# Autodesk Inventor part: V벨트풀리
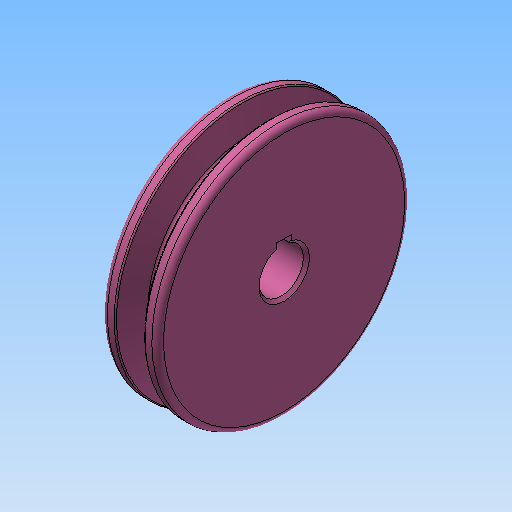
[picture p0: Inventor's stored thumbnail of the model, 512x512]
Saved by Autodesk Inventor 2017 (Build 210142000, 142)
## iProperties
Created: 2018-11
Part Number: V벨트풀리
Material: 알루미늄 6061
Document SubType Name: Modeling
Designer: mduedu
Density: 1 g/cm^3
Appearance: 분홍색
Author: mduedu
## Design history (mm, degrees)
sketch "스케치1"
  geometry: L1 (-9.5, 0)-(9.5, 0); L2 (9.5, 0)-(9.5, 42.7); L3 (9.5, 42.7)-(4.877, 42.7); L4 (-9.5, 42.7)-(-9.5, 0); L5 (-4.877, 42.7)-(-1.953, 33.7); L6 (-1.953, 33.7)-(1.953, 33.7); L7 (1.953, 33.7)-(4.877, 42.7); L8 (0, 0)-(0, 42.7); L9 (-9.5, 40)-(9.5, 40); L10 (-4.877, 42.7)-(-9.5, 42.7); L11 (4.877, 42.7)-(-4.877, 42.7); 3 further points
  constraints: 22 end point, 6 point on line, 4 parallel, 3 perpendicular, 2 midpoint, 1 coincident, 1 horizontal, 1 vertical, 1 other
  dimensions: "d2" = 19 distance of L2.end L4.start; "d3" = 80 diameter of L9 L1; "d4" = 36 deg angle of L7 L5; "d5" = 6.3 distance between parallel lines of L6 L9; "d6" = 8 distance of point (4, 40) point (-4, 40); "d27" = 2.7 distance between parallel lines of L3 L9
revolve "회전1" sketch "스케치1" stored, may be unused: angle "d7" = 90 deg
sketch "스케치2"
  geometry: L1 (-2.5, 7.071)-(2.5, 7.071); L2 (2.5, 7.071)-(2.5, 9.8); L3 (2.5, 9.8)-(-2.5, 9.8); L4 (-2.5, 9.8)-(-2.5, 7.071); A1 r 7.5 centre (0, 0) between (-2.5, 7.071) and (2.5, 7.071); 1 further point
  constraints: 8 end point, 2 parallel, 2 point on circle, 1 centre point, 1 coincident, 1 horizontal, 1 perpendicular
  dimensions: "d8" = 15 diameter of A1; "d10" = 17.3 dimension on A1 L3; "d11" = 5 distance of L2.end L3.end
extrude "돌출1" cut sketch "스케치2" stored distance "d12" = 10; taper "d13" = 0 deg
chamfer "모따기1" distance "d14" = 1; stored, may be unused: second distance "d15" = 2, angle "d16" = 45 deg
fillet "모깎기1" dims "d17" = 1, "d18" = 0.5, "d19" = 2
sketch "스케치3"
  geometry: C1 r 17.5 at (0, 0); C2 r 28.5 at (0, 0); 1 further point
  constraints: 2 centre point, 2 coincident
  dimensions: "d20" = 35 diameter of C1; "d23" = 57 diameter of C2
extrude "돌출2" cut sketch "스케치3" distance "d24" = 9.5; taper "d25" = 0 deg
fillet "모깎기2" dims "d26" = 3
chamfer "모따기2" distance "d28" = 0.5; stored, may be unused: second distance "d29" = 2, angle "d30" = 45 deg
node "솔리드1"
